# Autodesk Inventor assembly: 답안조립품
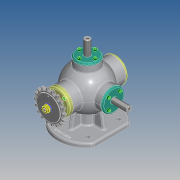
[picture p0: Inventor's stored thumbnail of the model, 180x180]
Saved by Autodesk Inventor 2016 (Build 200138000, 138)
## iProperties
Created: 2016-03
Part Number: 답안조립품
Document SubType Name: Assembly
Designer: Administrator
Mass: 3007.49 g
Surface Area: 2215.47 cm^2
Volume: 827.089 cm^3
Density: 3.63624 g/cm^3
Author: Administrator
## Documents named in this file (17)
- D:\360308V1005\360308V1005\답안조립품.iam
- D:\360308V1005\360308V1005\본체.ipt
- D:\360308V1005\360308V1005\축.ipt
- D:\360308V1005\360308V1005\키 3 x 3 x 12.ipt
- D:\360308V1005\360308V1005\베어링- 6202.ipt
- D:\360308V1005\360308V1005\뒤커버.ipt
- D:\360308V1005\360308V1005\앞커버.ipt
- D:\360308V1005\360308V1005\오일실.ipt
- D:\360308V1005\360308V1005\본체커버.ipt
- D:\360308V1005\360308V1005\슬라이드.ipt
- D:\360308V1005\360308V1005\스프링.ipt
- D:\360308V1005\360308V1005\스프링-2.ipt
- D:\360308V1005\360308V1005\슬라이드 커버.ipt
- D:\360308V1005\360308V1005\볼트 M4x0.7.ipt
- D:\360308V1005\360308V1005\너트-M8x1.ipt
- D:\360308V1005\360308V1005\스프로킷.ipt
- D:\360308V1005\360308V1005\와셔 8x17.ipt
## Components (17 placed, 1 different names)
1. M4x0.7x12:1
2. M4x0.7x12:2
3. M4x0.7x12:3
4. M4x0.7x12:4
5. M4x0.7x12:5
6. M4x0.7x12:6
7. M4x0.7x12:7
8. M4x0.7x12:8
9. M4x0.7x12:9
10. M4x0.7x12:10
11. M4x0.7x12:11
12. M4x0.7x12:12
13. M4x0.7x12:13
14. M4x0.7x12:14
15. M4x0.7x12:15
16. M4x0.7x12:16
17. M4x0.7x12:17
